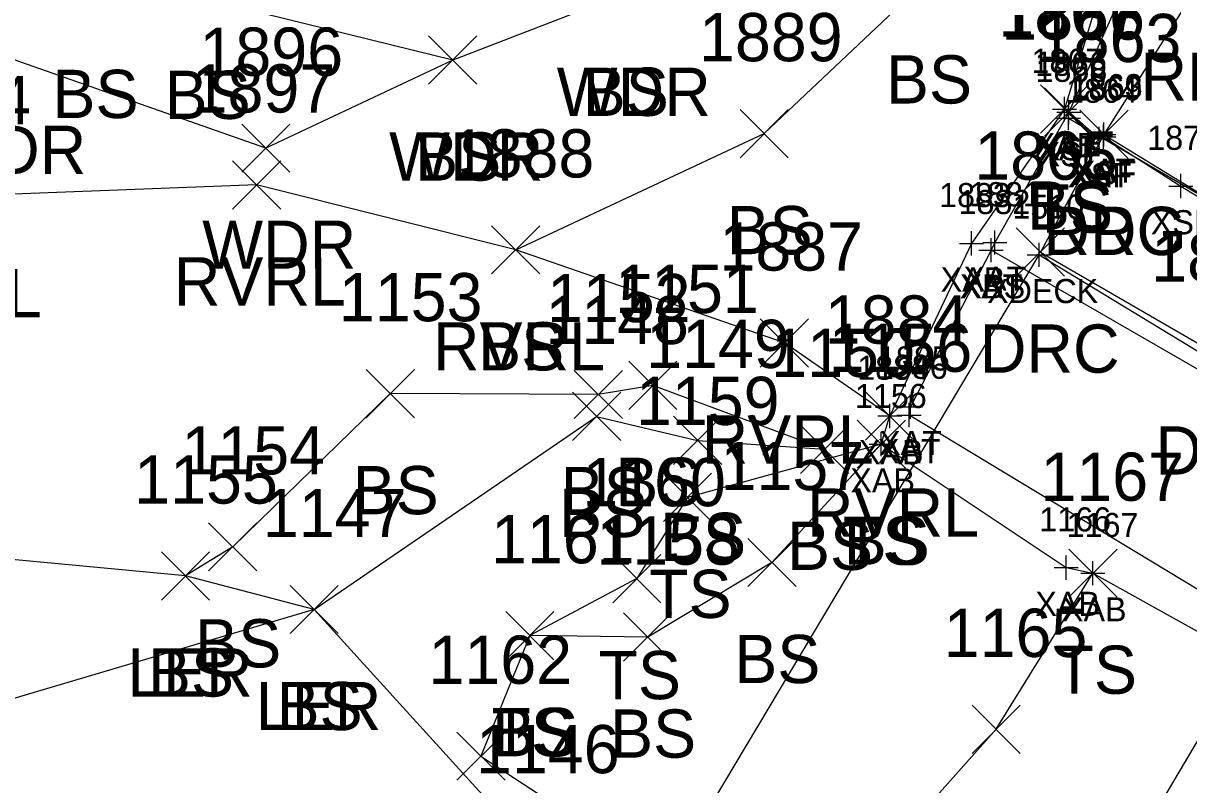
# Model space of a CAD drawing. Extents: x 1600281 to 1602254, y 862855 to 863227.
# Drawn here: x 1602017.47 to 1602065.77, y 863070.29 to 863101.85 of the extents above; entities that cross this region are included whole.
import ezdxf

# ---------------------------------------------------------------- set-up
doc = ezdxf.new("R2010")
doc.units = 0
for name, color, linetype in [('B_A', 7, 'Continuous'), ('B_I', 7, 'Continuous'), ('B_TIC', 7, 'Continuous'), ('BDEFAULT', 7, 'Continuous'), ('BELB', 7, 'Continuous'), ('BSE', 7, 'Continuous'), ('BSUBM', 7, 'Continuous'), ('L_A', 7, 'Continuous'), ('L_I', 7, 'Continuous'), ('L_TIC', 7, 'Continuous'), ('LARO', 7, 'Continuous'), ('LAWA', 7, 'Continuous'), ('LAWE', 7, 'Continuous'), ('LELB', 7, 'Continuous'), ('P_A', 7, 'Continuous'), ('P_I', 7, 'Continuous'), ('P_TIC', 7, 'Continuous'), ('PEU', 7, 'Continuous'), ('R_A', 7, 'Continuous'), ('R_I', 7, 'Continuous'), ('R_TIC', 7, 'Continuous'), ('RDP', 7, 'Continuous')]:
    doc.layers.add(name, color=color, linetype=linetype)

msp = doc.modelspace()

# ---------------------------------------------------------------- linework, layer by layer
at = {"layer": 'B_TIC'}
for p, q in [((1602060.624, 863098.298), (1602060.7, 863098.298)), ((1602060.793, 863097.925), (1602060.868, 863097.925)), ((1602060.802, 863098.174), (1602060.878, 863098.174)), ((1602060.802, 863098.174), (1602060.878, 863098.174)), ((1602062.059, 863097.058), (1602062.135, 863097.058)), ((1602062.059, 863097.058), (1602062.135, 863097.058)), ((1602062.246, 863097.151), (1602062.322, 863097.151)), ((1602062.257, 863097.245), (1602062.333, 863097.245)), ((1602065.445, 863095.106), (1602065.521, 863095.106)), ((1602056.774, 863092.73), (1602056.85, 863092.73)), ((1602057.734, 863092.767), (1602057.809, 863092.767)), ((1602057.578, 863092.444), (1602057.654, 863092.444)), ((1602057.578, 863092.444), (1602057.654, 863092.444)), ((1602059.573, 863092.252), (1602059.649, 863092.252)), ((1602054.238, 863085.957), (1602054.313, 863085.957)), ((1602053.382, 863085.572), (1602053.457, 863085.572)), ((1602053.382, 863085.572), (1602053.457, 863085.572)), ((1602054.181, 863085.612), (1602054.257, 863085.612)), ((1602054.181, 863085.612), (1602054.257, 863085.612)), ((1602053.031, 863084.403), (1602053.107, 863084.403)), ((1602053.031, 863084.403), (1602053.107, 863084.403)), ((1602060.696, 863079.286), (1602060.772, 863079.286)), ((1602061.801, 863079.055), (1602061.877, 863079.055))]:
    msp.add_line(p, q, dxfattribs=at)
for points in [[(1602060.621, 863097.798), (1602060.621, 863098.798)], [(1602060.789, 863097.425), (1602060.789, 863098.425)], [(1602060.799, 863097.674), (1602060.799, 863098.674)], [(1602060.799, 863097.674), (1602060.799, 863098.674)], [(1602060.121, 863098.298), (1602061.121, 863098.298)], [(1602060.289, 863097.925), (1602061.289, 863097.925)], [(1602060.299, 863098.174), (1602061.299, 863098.174)], [(1602060.299, 863098.174), (1602061.299, 863098.174)], [(1602062.056, 863096.558), (1602062.056, 863097.558)], [(1602062.056, 863096.558), (1602062.056, 863097.558)], [(1602062.243, 863096.651), (1602062.243, 863097.651)], [(1602062.254, 863096.745), (1602062.254, 863097.745)], [(1602061.556, 863097.058), (1602062.556, 863097.058)], [(1602061.556, 863097.058), (1602062.556, 863097.058)], [(1602061.743, 863097.151), (1602062.743, 863097.151)], [(1602061.754, 863097.245), (1602062.754, 863097.245)], [(1602065.442, 863094.606), (1602065.442, 863095.606)], [(1602064.942, 863095.106), (1602065.942, 863095.106)], [(1602056.771, 863092.23), (1602056.771, 863093.23)], [(1602057.73, 863092.267), (1602057.73, 863093.267)], [(1602056.271, 863092.73), (1602057.271, 863092.73)], [(1602057.23, 863092.767), (1602058.23, 863092.767)], [(1602057.575, 863091.944), (1602057.575, 863092.944)], [(1602057.575, 863091.944), (1602057.575, 863092.944)], [(1602059.57, 863091.752), (1602059.57, 863092.752)], [(1602057.075, 863092.444), (1602058.075, 863092.444)], [(1602057.075, 863092.444), (1602058.075, 863092.444)], [(1602059.07, 863092.252), (1602060.07, 863092.252)], [(1602054.234, 863085.457), (1602054.234, 863086.457)], [(1602053.378, 863085.072), (1602053.378, 863086.072)], [(1602053.378, 863085.072), (1602053.378, 863086.072)], [(1602053.734, 863085.957), (1602054.734, 863085.957)], [(1602054.178, 863085.112), (1602054.178, 863086.112)], [(1602054.178, 863085.112), (1602054.178, 863086.112)], [(1602052.878, 863085.572), (1602053.878, 863085.572)], [(1602052.878, 863085.572), (1602053.878, 863085.572)], [(1602053.678, 863085.612), (1602054.678, 863085.612)], [(1602053.678, 863085.612), (1602054.678, 863085.612)], [(1602053.028, 863083.903), (1602053.028, 863084.903)], [(1602053.028, 863083.903), (1602053.028, 863084.903)], [(1602052.528, 863084.403), (1602053.528, 863084.403)], [(1602052.528, 863084.403), (1602053.528, 863084.403)], [(1602060.693, 863078.786), (1602060.693, 863079.786)], [(1602061.798, 863078.555), (1602061.798, 863079.555)], [(1602060.193, 863079.286), (1602061.193, 863079.286)], [(1602061.298, 863079.055), (1602062.298, 863079.055)]]:
    msp.add_lwpolyline(points, dxfattribs=at)
at = {"layer": 'BDEFAULT'}
for points in [[(1602060.799, 863098.174), (1602060.789, 863097.925), (1602068.989, 863093.14), (1602077.184, 863088.071), (1602077.741, 863087.924)], [(1602062.056, 863097.058), (1602062.243, 863097.151), (1602065.442, 863095.106), (1602072.337, 863090.927), (1602076.071, 863088.93), (1602076.389, 863088.962)]]:
    msp.add_lwpolyline(points, dxfattribs=at)
at = {"layer": 'BELB'}
for points in [[(1602048.292, 863041.97), (1602034.377, 863049.991), (1602059.57, 863092.252), (1602073.185, 863083.996)], [(1602048.292, 863041.97), (1602073.185, 863083.996)]]:
    msp.add_lwpolyline(points, dxfattribs=at)
at = {"layer": 'BSE'}
msp.add_lwpolyline([(1602074.76, 863082.541), (1602057.575, 863092.444)], dxfattribs=at)
at = {"layer": 'BSUBM'}
for points in [[(1602060.621, 863098.298), (1602056.771, 863092.73), (1602053.378, 863085.572)], [(1602062.254, 863097.245), (1602062.056, 863097.058), (1602060.799, 863098.174), (1602057.73, 863092.767), (1602057.575, 863092.444), (1602054.234, 863085.957), (1602054.178, 863085.612)], [(1602053.028, 863084.403), (1602053.378, 863085.572)], [(1602081.255, 863078.736), (1602073.992, 863076.571), (1602070.997, 863075.947), (1602070.169, 863075.952), (1602054.178, 863085.612)], [(1602053.028, 863084.403), (1602060.693, 863079.286), (1602061.798, 863079.055), (1602069.576, 863074.729), (1602070.591, 863074.727), (1602071.854, 863075.326), (1602074.783, 863075.9), (1602081.333, 863077.74)]]:
    msp.add_lwpolyline(points, dxfattribs=at)
at = {"layer": 'L_TIC'}
for points in [[(1602034.268, 863099.33), (1602036.268, 863101.33)], [(1602036.268, 863099.33), (1602034.268, 863101.33)], [(1602034.268, 863099.33), (1602036.268, 863101.33)], [(1602036.268, 863099.33), (1602034.268, 863101.33)], [(1602059.621, 863097.298), (1602061.621, 863099.298)], [(1602061.621, 863097.298), (1602059.621, 863099.298)], [(1602059.799, 863097.174), (1602061.799, 863099.174)], [(1602061.799, 863097.174), (1602059.799, 863099.174)], [(1602047.175, 863096.278), (1602049.175, 863098.278)], [(1602049.175, 863096.278), (1602047.175, 863098.278)], [(1602026.521, 863095.676), (1602028.521, 863097.676)], [(1602028.521, 863095.676), (1602026.521, 863097.676)], [(1602026.14, 863094.153), (1602028.14, 863096.153)], [(1602028.14, 863094.153), (1602026.14, 863096.153)], [(1602036.877, 863091.461), (1602038.877, 863093.461)], [(1602038.877, 863091.461), (1602036.877, 863093.461)], [(1602036.877, 863091.461), (1602038.877, 863093.461)], [(1602038.877, 863091.461), (1602036.877, 863093.461)], [(1602048.014, 863087.599), (1602050.014, 863089.599)], [(1602050.014, 863087.599), (1602048.014, 863089.599)], [(1602042.561, 863085.843), (1602044.561, 863087.843)], [(1602044.561, 863085.843), (1602042.561, 863087.843)], [(1602031.676, 863085.499), (1602033.676, 863087.499)], [(1602033.676, 863085.499), (1602031.676, 863087.499)], [(1602040.3, 863085.463), (1602042.3, 863087.463)], [(1602042.3, 863085.463), (1602040.3, 863087.463)], [(1602040.232, 863084.555), (1602042.232, 863086.555)], [(1602042.232, 863084.555), (1602040.232, 863086.555)], [(1602052.378, 863084.572), (1602054.378, 863086.572)], [(1602054.378, 863084.572), (1602052.378, 863086.572)], [(1602044.418, 863083.561), (1602046.418, 863085.561)], [(1602046.418, 863083.561), (1602044.418, 863085.561)], [(1602052.028, 863083.403), (1602054.028, 863085.403)], [(1602054.028, 863083.403), (1602052.028, 863085.403)], [(1602052.028, 863083.403), (1602054.028, 863085.403)], [(1602054.028, 863083.403), (1602052.028, 863085.403)], [(1602049.679, 863083.191), (1602051.679, 863085.191)], [(1602051.679, 863083.191), (1602049.679, 863085.191)], [(1602043.996, 863081.199), (1602045.996, 863083.199)], [(1602045.996, 863081.199), (1602043.996, 863083.199)], [(1602025.15, 863079.149), (1602027.15, 863081.149)], [(1602027.15, 863079.149), (1602025.15, 863081.149)], [(1602047.494, 863078.498), (1602049.494, 863080.498)], [(1602049.494, 863078.498), (1602047.494, 863080.498)], [(1602060.798, 863078.055), (1602062.798, 863080.055)], [(1602062.798, 863078.055), (1602060.798, 863080.055)], [(1602023.193, 863077.94), (1602025.193, 863079.94)], [(1602025.193, 863077.94), (1602023.193, 863079.94)], [(1602023.193, 863077.94), (1602025.193, 863079.94)], [(1602025.193, 863077.94), (1602023.193, 863079.94)], [(1602041.897, 863077.832), (1602043.897, 863079.832)], [(1602043.897, 863077.832), (1602041.897, 863079.832)], [(1602028.525, 863076.549), (1602030.525, 863078.549)], [(1602030.525, 863076.549), (1602028.525, 863078.549)], [(1602028.525, 863076.549), (1602030.525, 863078.549)], [(1602030.525, 863076.549), (1602028.525, 863078.549)], [(1602028.525, 863076.549), (1602030.525, 863078.549)], [(1602030.525, 863076.549), (1602028.525, 863078.549)], [(1602028.525, 863076.549), (1602030.525, 863078.549)], [(1602030.525, 863076.549), (1602028.525, 863078.549)], [(1602037.461, 863075.466), (1602039.461, 863077.466)], [(1602039.461, 863075.466), (1602037.461, 863077.466)], [(1602037.461, 863075.466), (1602039.461, 863077.466)], [(1602039.461, 863075.466), (1602037.461, 863077.466)], [(1602042.346, 863075.407), (1602044.346, 863077.407)], [(1602044.346, 863075.407), (1602042.346, 863077.407)], [(1602056.788, 863071.582), (1602058.788, 863073.582)], [(1602058.788, 863071.582), (1602056.788, 863073.582)], [(1602035.437, 863070.468), (1602037.437, 863072.468)], [(1602037.437, 863070.468), (1602035.437, 863072.468)]]:
    msp.add_lwpolyline(points, dxfattribs=at)
at = {"layer": 'LARO'}
msp.add_lwpolyline([(1602088.591, 863055.936), (1602084.205, 863057.115), (1602072.763, 863055.569), (1602061.695, 863058.699), (1602046.297, 863060.847), (1602041.29, 863063.794), (1602038.414, 863067.763), (1602029.525, 863077.549), (1602024.193, 863078.94), (1602013.468, 863079.959), (1602006.072, 863081.659), (1601997.978, 863081.824), (1601978.825, 863086.781)], dxfattribs=at)
at = {"layer": 'LAWA'}
msp.add_lwpolyline([(1602042.214, 863103.013), (1602035.268, 863100.33), (1602027.521, 863096.676), (1602016.33, 863100.607), (1602006.455, 863104.438)], dxfattribs=at)
at = {"layer": 'LAWE'}
msp.add_lwpolyline([(1602053.378, 863085.572), (1602049.014, 863088.599), (1602037.877, 863092.461), (1602027.14, 863095.153), (1602014.534, 863094.667), (1602004.691, 863100.661), (1601989.462, 863105.807), (1601980.589, 863100.305)], dxfattribs=at)
at = {"layer": 'LELB'}
for points in [[(1602035.268, 863100.33), (1602024.883, 863102.888), (1602020.237, 863102.925), (1602006.781, 863113.183), (1601994.721, 863114.246), (1601987.36, 863112.239), (1601977.428, 863113.016), (1601970.299, 863112.715), (1601965.747, 863121.079), (1601960.048, 863139.675)], [(1602241.548, 863072.298), (1602203.833, 863084.044), (1602184.904, 863092.774), (1602150.824, 863109.068), (1602129.545, 863119.041), (1602102.3, 863128.31), (1602095.851, 863125.022), (1602082.9, 863122.059), (1602071.558, 863117.437), (1602069.712, 863115.849), (1602064.38, 863110.746), (1602060.621, 863098.298)], [(1602069.712, 863115.849), (1602065.759, 863109.254), (1602060.799, 863098.174)], [(1602037.877, 863092.461), (1602048.175, 863097.278), (1602054.778, 863103.527)], [(1602029.525, 863077.549), (1602041.232, 863085.555), (1602045.418, 863084.561), (1602050.679, 863084.191), (1602043.561, 863086.843), (1602041.3, 863086.463), (1602032.676, 863086.499), (1602026.15, 863080.149), (1602024.193, 863078.94)], [(1602053.028, 863084.403), (1602044.996, 863082.199), (1602042.897, 863078.832), (1602038.461, 863076.466), (1602036.437, 863071.468), (1602049.302, 863063.059), (1602059.529, 863059.725), (1602064.631, 863062.934), (1602075.728, 863060.869), (1602085.918, 863063.754)], [(1602053.028, 863084.403), (1602048.494, 863079.498), (1602043.346, 863076.407), (1602038.461, 863076.466)], [(1602049.302, 863063.059), (1602057.788, 863072.582), (1602061.798, 863079.055)], [(1602029.525, 863077.549), (1602013.803, 863072.893), (1602011.17, 863068.044), (1602010.46, 863065.672), (1602010.309, 863056.702), (1602006.228, 863059.152), (1602004.602, 863065.455), (1602000.504, 863068.388)]]:
    msp.add_lwpolyline(points, dxfattribs=at)
at = {"layer": 'P_TIC'}
for points in [[(1602061.254, 863096.245), (1602063.254, 863098.245)], [(1602063.254, 863096.245), (1602061.254, 863098.245)]]:
    msp.add_lwpolyline(points, dxfattribs=at)
at = {"layer": 'PEU'}
msp.add_lwpolyline([(1602239.323, 863063.193), (1602201.856, 863077.578), (1602181.734, 863084.138), (1602148.756, 863103.129), (1602126.101, 863112.297), (1602096.314, 863123.237), (1602085.65, 863117.237), (1602075.424, 863112.315), (1602066.282, 863103.641), (1602062.254, 863097.245), (1602069.562, 863092.761), (1602076.187, 863089.042)], dxfattribs=at)
at = {"layer": 'R_TIC'}
for points in [[(1602061.254, 863096.245), (1602063.254, 863098.245)], [(1602063.254, 863096.245), (1602061.254, 863098.245)], [(1602058.623, 863091.367), (1602060.623, 863093.367)], [(1602060.623, 863091.367), (1602058.623, 863093.367)]]:
    msp.add_lwpolyline(points, dxfattribs=at)
at = {"layer": 'RDP'}
msp.add_lwpolyline([(1602062.254, 863097.245), (1602059.623, 863092.367), (1602066.905, 863088.144), (1602073.232, 863084.216), (1602076.187, 863089.042)], dxfattribs=at)

# ---------------------------------------------------------------- texts
at = {"layer": 'B_A'}
for s, p in [('XAB', (1602059.341, 863096.298)), ('XAT', (1602059.503, 863096.174)), ('XSF', (1602059.549, 863095.925)), ('XSF', (1602059.558, 863096.174)), ('XAT', (1602060.76, 863095.058)), ('XSF', (1602060.815, 863095.058)), ('XAT', (1602060.959, 863095.245)), ('XSF', (1602061.003, 863095.151)), ('XSF', (1602064.202, 863093.106)), ('XAB', (1602055.491, 863090.73)), ('XAT', (1602056.435, 863090.767)), ('XAT', (1602056.279, 863090.444)), ('XBS', (1602056.315, 863090.444)), ('XDECK', (1602057.412, 863090.252)), ('XAT', (1602052.939, 863083.957)), ('XAB', (1602052.099, 863083.572)), ('XAB', (1602052.099, 863083.572)), ('XAT', (1602052.883, 863083.612)), ('XAT', (1602052.883, 863083.612)), ('XAB', (1602051.748, 863082.403)), ('XAB', (1602051.748, 863082.403)), ('XAB', (1602059.413, 863077.286)), ('XAB', (1602060.518, 863077.055))]:
    msp.add_text(s, height=1, dxfattribs=at).set_placement(p)
at = {"layer": 'B_I'}
for s, p in [('1867', (1602059.251, 863099.798)), ('1866', (1602059.401, 863099.674)), ('1866', (1602059.401, 863099.674)), ('1868', (1602059.419, 863099.425)), ('1864', (1602060.686, 863098.558)), ('1864', (1602060.686, 863098.558)), ('1869', (1602060.869, 863098.651)), ('1863', (1602060.884, 863098.745)), ('1870', (1602064.052, 863096.606)), ('1883', (1602055.424, 863094.23)), ('1882', (1602056.228, 863093.944)), ('1882', (1602056.228, 863093.944)), ('1881', (1602056.667, 863094.267)), ('1510', (1602058.463, 863093.752)), ('1885', (1602052.888, 863087.457)), ('1884', (1602052.032, 863087.072)), ('1884', (1602052.032, 863087.072)), ('1886', (1602052.804, 863087.112)), ('1886', (1602052.804, 863087.112)), ('1156', (1602051.937, 863085.903)), ('1156', (1602051.937, 863085.903)), ('1166', (1602059.579, 863080.786)), ('1167', (1602060.711, 863080.555))]:
    msp.add_text(s, height=1, dxfattribs=at).set_placement(p)
at = {"layer": 'L_A'}
for s, p in [('BS', (1602053.219, 863098.527)), ('BS', (1602053.219, 863098.527)), ('BS', (1602018.677, 863097.925)), ('BS', (1602023.324, 863097.888)), ('WDR', (1602039.577, 863098.013)), ('BS', (1602040.655, 863098.013)), ('WDR', (1602013.693, 863095.607)), ('WDR', (1602032.631, 863095.33)), ('BS', (1602033.709, 863095.33)), ('TS', (1602059.208, 863093.174)), ('BS', (1602059.062, 863093.298)), ('BS', (1602046.616, 863092.278)), ('WDR', (1602024.883, 863091.676)), ('RVRL', (1602023.707, 863090.153)), ('RVRL', (1602011.101, 863089.667)), ('RVRL', (1602034.444, 863087.461)), ('BS', (1602036.318, 863087.461)), ('RVRL', (1602045.581, 863083.599)), ('BS', (1602042.002, 863081.843)), ('BS', (1602031.117, 863081.499)), ('BS', (1602039.741, 863081.463)), ('BS', (1602039.673, 863080.555)), ('RVRL', (1602049.945, 863080.572)), ('BS', (1602043.859, 863079.561)), ('TS', (1602051.437, 863079.403)), ('BS', (1602051.469, 863079.403)), ('BS', (1602049.12, 863079.191)), ('TS', (1602043.406, 863077.199)), ('BS', (1602024.591, 863075.149)), ('BS', (1602046.935, 863074.498)), ('LER', (1602021.776, 863073.94)), ('BS', (1602022.634, 863073.94)), ('TS', (1602041.307, 863073.832)), ('TS', (1602060.207, 863074.055)), ('LER', (1602027.107, 863072.549)), ('BS', (1602027.966, 863072.549)), ('BS', (1602027.966, 863072.549)), ('BS', (1602027.966, 863072.549)), ('TS', (1602036.871, 863071.466)), ('BS', (1602036.902, 863071.466)), ('BS', (1602041.787, 863071.407))]:
    msp.add_text(s, height=2, dxfattribs=at).set_placement(p)
at = {"layer": 'L_I'}
for s, p in [('1867', (1602057.881, 863101.298)), ('1866', (1602058.003, 863101.174)), ('1889', (1602045.475, 863100.278)), ('1896', (1602024.773, 863099.676)), ('1897', (1602024.447, 863098.153)), ('1954', (1602011.841, 863097.667)), ('1954', (1602011.841, 863097.667)), ('1888', (1602035.184, 863095.461)), ('1888', (1602035.184, 863095.461)), ('1887', (1602046.321, 863091.599)), ('1151', (1602042.002, 863089.843)), ('1153', (1602030.55, 863089.499)), ('1152', (1602039.174, 863089.463)), ('1884', (1602050.685, 863088.572)), ('1148', (1602039.106, 863088.555)), ('1149', (1602043.284, 863087.561)), ('1150', (1602048.466, 863087.191)), ('1156', (1602050.847, 863087.403)), ('1156', (1602050.847, 863087.403)), ('1159', (1602042.862, 863085.199)), ('1154', (1602024.024, 863083.149)), ('1157', (1602046.368, 863082.498)), ('1155', (1602022.067, 863081.94)), ('1155', (1602022.067, 863081.94)), ('1160', (1602040.637, 863081.832)), ('1167', (1602059.624, 863082.055)), ('1147', (1602027.399, 863080.549)), ('1147', (1602027.399, 863080.549)), ('1147', (1602027.399, 863080.549)), ('1147', (1602027.399, 863080.549)), ('1161', (1602036.855, 863079.466)), ('1161', (1602036.855, 863079.466)), ('1158', (1602041.22, 863079.407)), ('1165', (1602055.615, 863075.582)), ('1162', (1602034.264, 863074.468)), ('1146', (1602036.233, 863070.763)), ('1146', (1602036.233, 863070.763))]:
    msp.add_text(s, height=2, dxfattribs=at).set_placement(p)
at = {"layer": 'P_A'}
for p in [(1602063.771, 863098.641), (1602059.742, 863092.245)]:
    msp.add_text('RDG', height=2, dxfattribs=at).set_placement(p)
at = {"layer": 'P_I'}
msp.add_text('1863', height=2, dxfattribs=at).set_placement((1602059.514, 863100.245))
at = {"layer": 'R_A'}
for p in [(1602059.742, 863092.245), (1602057.111, 863087.367), (1602064.393, 863083.144)]:
    msp.add_text('DRC', height=2, dxfattribs=at).set_placement(p)
at = {"layer": 'R_I'}
for s, p in [('1863', (1602059.514, 863100.245)), ('1865', (1602056.883, 863095.367)), ('1877', (1602064.212, 863091.144))]:
    msp.add_text(s, height=2, dxfattribs=at).set_placement(p)

doc.saveas('drawing.dxf')
